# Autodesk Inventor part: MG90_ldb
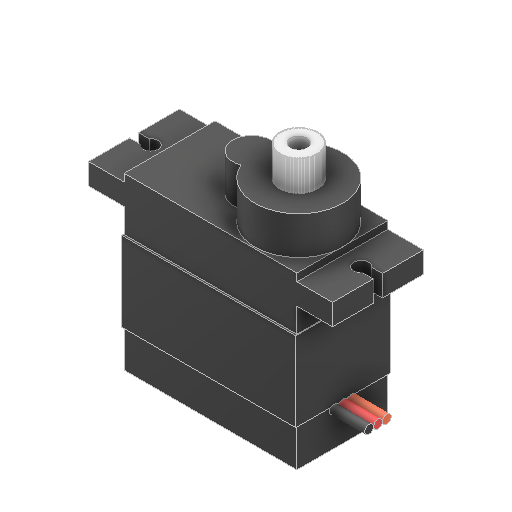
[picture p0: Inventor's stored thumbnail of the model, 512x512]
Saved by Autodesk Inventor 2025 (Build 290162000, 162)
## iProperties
Created: 2019-07
Part Number: MG90_ldb
Material: Alluminio 6061
Document SubType Name: Modeling
Designer: Ryzen5700u
Density: 2.7 g/cm^3
Appearance: Default
Author: Ryzen5700u
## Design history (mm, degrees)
feature "Solido1"
node "Solido2"
